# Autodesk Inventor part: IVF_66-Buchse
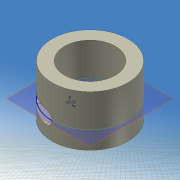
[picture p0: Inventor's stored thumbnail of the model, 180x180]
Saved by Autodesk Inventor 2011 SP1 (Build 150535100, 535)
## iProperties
Created: 2012-01
Part Number: IVF_66-Buchse
Material: Sondermaterial siehe Beschreibung
Document SubType Name: Modellierung
Designer: Gawin
Surface Area: 39.6631 cm^2
Volume: 7.5536 cm^3
Author: Gawin
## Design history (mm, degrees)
sketch "Skizze1"
  geometry: C1 r 15 at (0, 0); C2 r 10 at (0, 0); 1 further point
  constraints: 2 centre point, 2 coincident
  dimensions: "d0" = 30 diameter of C1; "d1" = 20 diameter of C2
extrude "Extrusion1" new body sketch "Skizze1" stored distance "d2" = 20; taper "d3" = 0 deg
workplane "Arbeitsebene1"
sketch "Skizze2"
  geometry: L1 (0, 0)-(0, -15); L2 (0, 0)-(12.99, -7.5); L3 (12.99, -7.5)-(8.66, -5); L4 (0, -15)-(0, -10); A1 r 15 centre (0, 0) between (0, -15) and (12.99, -7.5) reference; A2 r 15 centre (0, 0) between (0, -15) and (12.99, -7.5) reference; A3 r 10 centre (0, 0) between (0, -10) and (8.66, -5); A4 r 15 centre (0, 0) between (0, -15) and (12.99, -7.5); 2 further points
  constraints: 8 end point, 8 point on circle, 2 centre point, 2 coincident, 2 collinear, 1 point on line, 1 vertical, 2 other
  dimensions: "d5" = 60 deg angle of L1 L2
extrude "Extrusion2" cut sketch "Skizze2" taper "d7" = 0 deg; stored distance "Breite" = 5
fillet "Rundung1" dims "d8" = 2.5 (= 0.5 x Breite)
node "Volumenkörper1"
node "Projizierte Kontur1"
other parameters: "Stärke" = 1 (derived), "KFaktor" = 4.4, "Biegeradius" = 2.5 (derived), "BreiteBiegungsfreistellung" = 1 (= Stärke), "TiefeBiegungsfreistellung" = 0.5 (= 0.5 x Stärke), "GrößeEckenfreistellung" = 2 (= 2 x Stärke), "AbstandVerbindung" = 0.01, "MinimalRest" = 2 (= 2 x Stärke), "Übergangsradius" = 2.5 (= Biegeradius), "JacobiRadiusGröße" = 2.5 (= Biegeradius), "Abstandsgröße" = 0.1 (derived), "d4" = -7
